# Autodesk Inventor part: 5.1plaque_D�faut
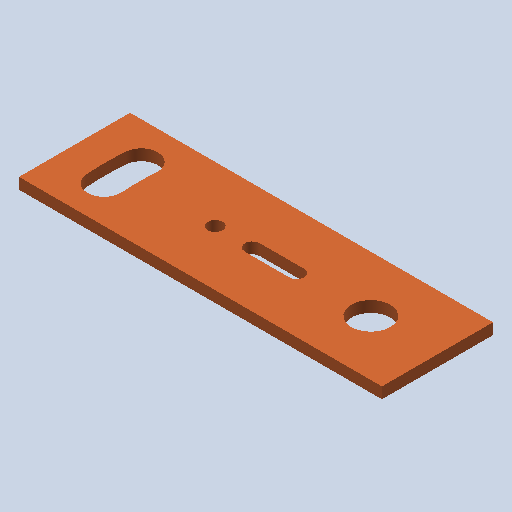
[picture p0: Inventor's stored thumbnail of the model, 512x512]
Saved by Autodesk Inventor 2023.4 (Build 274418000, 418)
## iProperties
Created: 2011-01
Part Number: 5.1plaque_D�faut
Document SubType Name: Modeling
Designer: eric
Density: 1 g/cm^3
Mass: 7.87973 g
Surface Area: 64.1239 cm^2
Volume: 7.87973 cm^3
Material: Générique
Appearance: 255,128,64_1
Author: eric
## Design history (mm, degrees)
feature "Base1"
node "Corps solides"
node "Corps surfaciques"
node "Solide1"
